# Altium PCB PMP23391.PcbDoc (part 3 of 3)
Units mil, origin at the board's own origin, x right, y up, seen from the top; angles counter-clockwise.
Board outline 5500 x 3250 mil, 2 copper layers (Top Layer, Bottom Layer), stack 62 mil thick; 163 components, 101 nets, 543 pads, 307 vias.
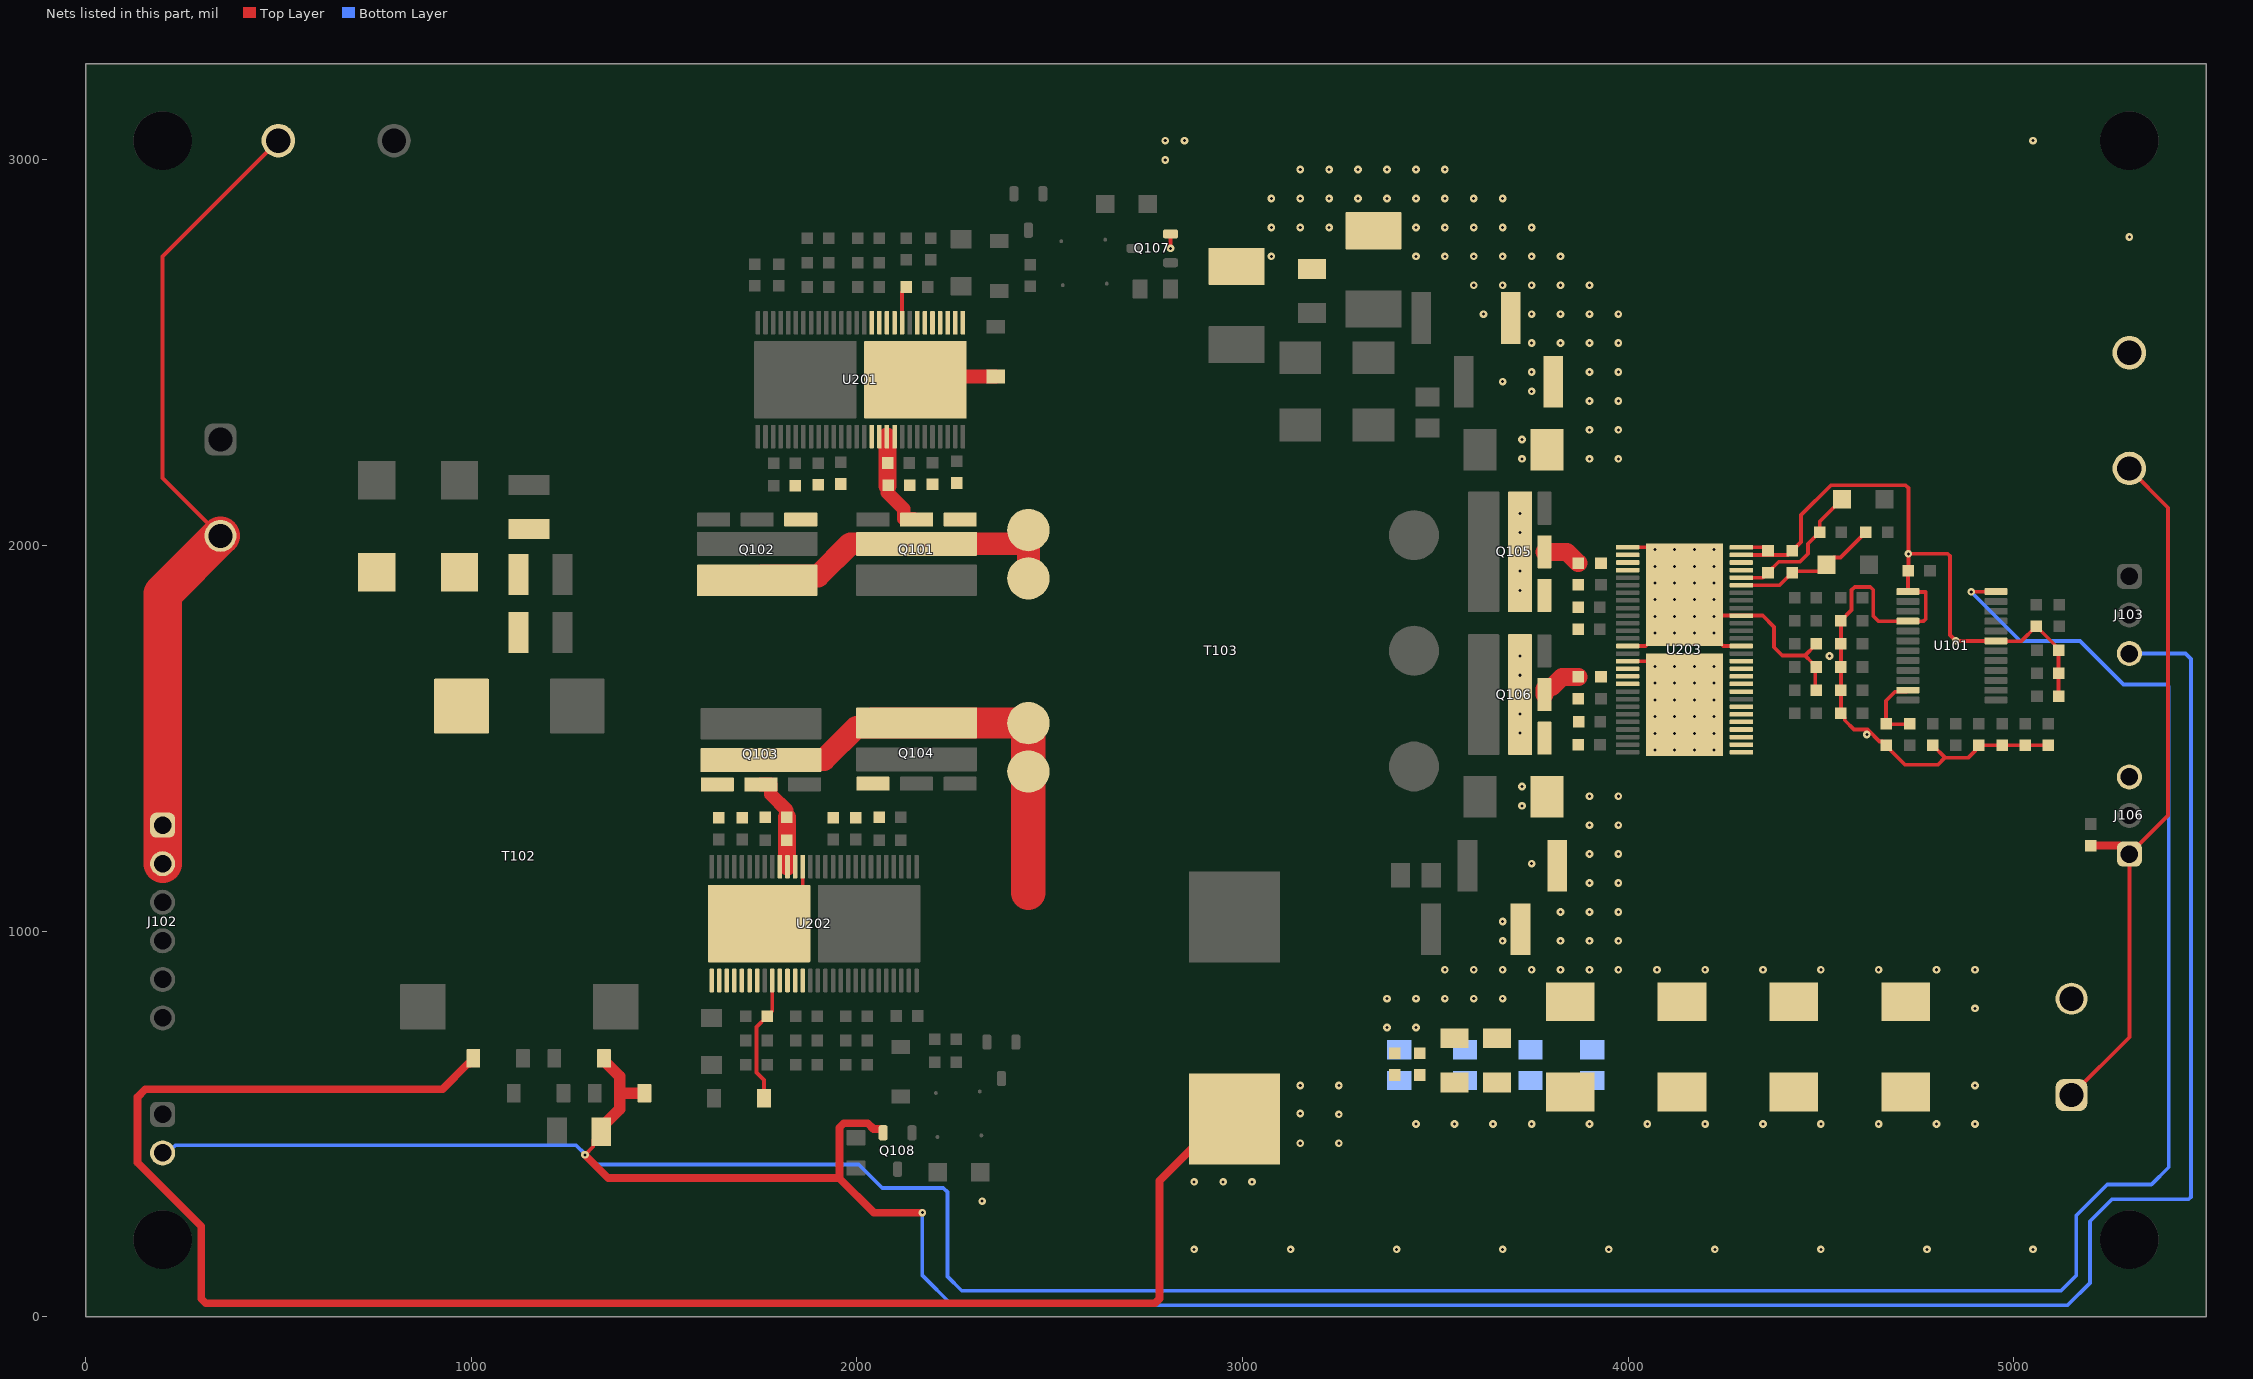
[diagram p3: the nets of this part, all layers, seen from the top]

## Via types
v1: diameter 20, hole 8, Top Layer to Bottom Layer, 211 vias
v2: diameter 19.68, hole 7.87, Top Layer to Bottom Layer, tented both sides, 96 vias

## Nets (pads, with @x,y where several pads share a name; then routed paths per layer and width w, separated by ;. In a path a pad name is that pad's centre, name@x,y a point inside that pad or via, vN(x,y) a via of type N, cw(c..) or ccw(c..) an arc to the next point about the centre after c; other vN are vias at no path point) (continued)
SGND: C101.2 C104.1 C105.1 C106.2 C109.1 C110.2 C111.2 C112.2 C113.1 C114.1 C115.2 C116.2 C119.2 C120.2 C121.2 C122.2 C123.2 C124.2 C125.2 C211.2 C212.1 C213.1 C214.1 C301.2 C302.2 C303.2 C304.2 D103.2 D104.2 D106.2 D107.2 J103.3 J104.2 J105.2 J106.3 Q105.4 Q105.5 Q106.4 Q106.5 Q107.2 Q108.2 R101.1 R102.1 R103.1 R104.2 R105.2 R106.1 R109.2 R110.2 R117.1 R118.1 R119.1 R120.1 R121.2 R126.1 R230.2 R235.2 R236.2 R301.2 TP104.1 U101.7 U101.12 U101.13 U101.16 U203.1 U203.2 U203.3 U203.4 U203.5 U203.6 U203.7 U203.9 U203.10 U203.11 U203.12 U203.13 U203.15 U203.19 U203.25 U203.26 U203.27 U203.28 U203.29 U203.30 U203.31 U203.32 U203.42 U203.44 U203.45 U203.46 U203.47 U203.57 U203.58 | length 18652.7
  Top Layer w9.84: v1(1295,420) 1316.42,441.42 1316.42,459.33 R103.1@1337.09,480 ; v1(2813.58,2770.82) Q107.2@2813.58,2808.22 ; v2(4223.15,1816.32) 4225.12,1818.29 U203.19@4294.02,1818.29 4349.13,1818.29 4378.66,1788.76 4378.66,1736.34 4400,1715 4458.89,1715 ; U203.27@4294.02,1975.77 4415.62,1975.77 C114.1@4425.91,1986.05 4448.85,2008.99 4448.85,2079.3 4525.96,2156.42 4719.94,2156.42 4727,2149.35 v1(4727,1978.61) C104.1@4727,1935 4725.83,1933.83 U101.13@4725.83,1880.75 ; U203.28@4294.02,1995.45 4353.51,1995.45 C113.1@4362.91,1986.05 ; C212.1@4485.4,1615.53 C211.2@4485.4,1678.52 ; R230.2@4485.4,1741.51 4458.89,1715 ; C211.2@4488,1685.89 4487.11,1685.89 4477.92,1695.08 4477.92,1695.97 4458.89,1715 ; R126.1@4668.74,1480.74 4718,1431.48 4803.48,1431.48 4822,1450 ; R126.1@4670,1482 4659.92,1492.08 4652.38,1492.08 4621.51,1522.94 4586.33,1522.94 4562.08,1547.2 4562.08,1554.92 C106.2@4552,1565 R110.2@4552,1625 R109.2@4552,1745 C110.2@4552,1805 4579.8,1832.8 4579.8,1884.89 4587.7,1892.8 4628.3,1892.8 4635.8,1885.3 4635.8,1817 4648.82,1803.98 U101.16@4725.83,1803.98 4766.38,1803.98 4772.14,1809.74 4772.14,1879.53 U101.13@4727.04,1879.53 ; C112.2@4790,1482 4822,1450 ; v1(4890,1880) 4890.37,1880.37 4953.8,1880.37 U101.12@4954.17,1880.75 ; R102.1@5090,1482 C111.2@4910,1482 4899.92,1471.92 4899.92,1467.28 4882.64,1450 4822,1450
  Top Layer w10: U203.44@3998.74,1700.18 U203.57@4050.98,1700.18 ; U203.42@3998.74,1739.55 4045.98,1739.55 4069.61,1763.17 v2(4069.61,1773.01) ; U203.29@3998.74,1995.45 U203.58@4063.7,1995.45 ; U203.58@4146.38,1872.42 4146.38,1839.94 4246.77,1739.55 U203.15@4294.02,1739.55 ; v1(4727,1978.61) 4829.14,1978.61 4835,1972.75 4835,1767.8 v1(4850,1752.8) U101.7@4954.17,1752.8 ; U101.7@4954.17,1751.68 5019.39,1751.68 C101.2@5058.6,1790.89 5106.6,1742.89 5106.6,1738.89 R106.1@5116.6,1728.89 R104.2@5116.6,1608.89
  Top Layer w20: v1(1295,420) 1355.31,359.69 1955.02,359.69 ; Q108.2@2068.39,477.24 2068.39,485.12 2066.57,486.93 2043.36,486.93 2028.36,501.93 1966.64,501.93 1955.02,490.31 1955.02,359.69 ; v1(2170,270) 2044.71,270 1955.02,359.69
  Top Layer w30: R103.1@1337.09,480 1337.09,490.83 1385,538.74 1385,581 ; D103.2@1344.37,670 1344.37,663.9 1385,623.27 1385,581 ; D104.2@1449.37,580 1386,580 1385,581
  Top Layer w47.24: Q106.5@3783.19,1613.64 3783.19,1627.38 3788.82,1633.01 3802.56,1633.01 3828.83,1659.28 R235.2@3870.79,1659.28 ; Q105.5@3783.19,1983.64 3841.7,1983.64 R236.2@3870.79,1954.55
  Bottom Layer w9.84: J104.2@200,425 213.32,425 233.32,445 1272.24,445 1295,422.24 v1(1295,420) 1320,395 2005.26,395 2065.93,334.33 2224.23,334.33 2235,323.57 2235,104.83 2272.04,67.8 5122.96,67.8 5157.8,102.63 5157.8,102.8 5162.2,107.2 5162.2,262.37 5242.63,342.8 5357.03,342.8 5402.2,387.97 5402.2,1634.23 5396.44,1640 5285,1640 5282.8,1642.2 5282.63,1642.2 5171.95,1752.89 5017.11,1752.89 v1(4890,1880) ; v1(2170,270) 2170,107.27 2247.35,29.92 5139.92,29.92 5197.8,87.8 5197.8,247.63 5255.17,305 5454.23,305 5460,310.77 5460,1705.49 5445.49,1720 J103.3@5300,1720
  other v1: 2325,300 3375,750 3450,750 4900,800 3375,825 3450,825 3525,825 3600,825 3675,825 3525,900 3600,900 3675,900 3750,900 3825,900 3900,900 3975,900 4075,900 4200,900 4350,900 4500,900 4650,900 4800,900 4900,900 3675,975 3825,975 3900,975 3975,975 3675,1025 3825,1050 3900,1050 3975,1050 3900,1125 3975,1125 3750,1175 3900,1200 3975,1200 3900,1275 3975,1275 3725,1325 3900,1350 3975,1350 3725,1375 4619.38,1510 3720.18,1513.64 3720.18,1563.64 3720.18,1613.64 3720.18,1663.64 3720.18,1713.64 4522.59,1713.64 3720.18,1883.64 3720.18,1933.64 3720.18,1983.64 3720.18,2033.64 3720.18,2083.64 3725,2225 3900,2225 3975,2225 3725,2275 3900,2300 3975,2300 3900,2375 3975,2375 3750,2400 3675,2425 3750,2450 3900,2450 3975,2450 3750,2525 3825,2525 3900,2525 3975,2525 3625,2600 3750,2600 3825,2600 3900,2600 3975,2600 3600,2675 3675,2675 3750,2675 3825,2675 3900,2675 3075,2750 3450,2750 3525,2750 3600,2750 3675,2750 3750,2750 3825,2750 5300,2800 3075,2825 3150,2825 3225,2825 3450,2825 3525,2825 3600,2825 3675,2825 3750,2825 3075,2900 3150,2900 3225,2900 3300,2900 3375,2900 3450,2900 3525,2900 3599.69,2900 3675,2900 3150,2975 3225,2975 3300,2975 3375,2975 3450,2975 3525,2975 2800,3000 2800,3050 2850,3050 5050,3050
  other v2: 4069.61,1469.86 4120.79,1469.86 4171.97,1469.86 4223.15,1469.86 4069.61,1513.17 4120.79,1513.17 4171.97,1513.17 4223.15,1513.17 4069.61,1556.47 4120.79,1556.47 4171.97,1556.47 4223.15,1556.47 4069.61,1599.78 4120.79,1599.78 4171.97,1599.78 4223.15,1599.78 4069.61,1643.09 4120.79,1643.09 4171.97,1643.09 4223.15,1643.09 4069.61,1686.4 4120.79,1686.4 4171.97,1686.4 4223.15,1686.4 4120.79,1773.01 4171.97,1773.01 4223.15,1773.01 4069.61,1816.32 4120.79,1816.32 4171.97,1816.32 4069.61,1859.62 4120.79,1859.62 4171.97,1859.62 4223.15,1859.62 4069.61,1902.93 4120.79,1902.93 4171.97,1902.93 4223.15,1902.93 4069.61,1946.24 4120.79,1946.24 4171.97,1946.24 4223.15,1946.24 4069.61,1989.55 4120.79,1989.55 4171.97,1989.55 4223.15,1989.55
SRA: C114.2 D108.1 R114.1 U203.23 | length 353.3
  Top Layer w9.84: U203.23@4294.02,1897.03 4392.88,1897.03 4429.36,1933.51 D108.1@4494.84,1933.51 ; D108.1@4514.88,1950 4533.58,1968.7 4550.7,1968.7 R114.1@4617,2035
SRB: C113.2 D105.1 R113.1 U203.24 | length 376.2
  Top Layer w9.84: U203.24@4294.02,1916.71 4349.57,1916.71 C113.2@4362.91,1930.05 4390.71,1957.84 4445.8,1957.84 4466.56,1978.61 4466.56,2004.56 R113.1@4497,2035 4497,2062.12 D105.1@4554.88,2120
SW_A: Q101.4 Q102.3 T103.1 T103.2 | length 821.7
  Top Layer w59.06: Q102.3@1743.58,1910 1754.55,1920.96 1899.36,1920.96 1983.38,2004.98 Q101.4@2145.65,2004.98 ; Q101.4@2155,2004.49 2444.49,2004.49 2445,2005 T103.2@2445,1914.92
SW_B: Q103.4 Q104.3 T103.5 T103.6 | length 1168.3
  Top Layer w59.06: Q103.4@1751.46,1443.54 1752.93,1445.02 1915.2,1445.02 1999.22,1529.04 Q104.3@2041.48,1529.04
  Top Layer w80: Q104.3@2040.98,1540.49 2041.48,1540 T103.5@2444.33,1540
  Top Layer w90: 2445,1100 T103.6@2445,1414.13 T103.5@2445,1539.33
VG_HOA: Q101.1 R208.1 R209.1 R212.1
VG_HOB: Q103.1 R221.1 R222.1 R225.1
VG_LOA: Q102.1 R210.1 R211.1 R213.1
VG_LOB: Q104.1 R223.1 R224.1 R226.1
VG_SRA: Q105.1 R233.1 R234.1 R236.1
VG_SRB: Q106.1 R231.1 R232.1 R235.1
VIN: C102.1 C103.1 C107.1 C108.1 J101.2 J102.1 J102.2 R108.1 T102.2 TP101.1 | length 2123.5
  Top Layer w10: J101.2@350,2025 200,2175 200,2750 TP101.1@500,3050
  Top Layer w100: J102.2@200,1175 J102.1@200,1275 200,1875 J101.2@350,2025
VOUT: C115.1 C116.1 C119.1 C120.1 C121.1 C123.1 C124.1 C125.1 C301.1 C302.1 C303.1 C304.1 D101.1 J105.1 J106.1 L101.2 R124.2 TP103.1 | length 6413.8
  Top Layer w10: J105.1@5150,575 5300,725 J106.1@5300,1200 5400,1300 5400,2098.14 5300,2198.14 TP103.1@5300,2200
  Top Layer w20: D101.1@1005.63,670 1005.63,663.9 997.72,655.98 991.61,655.98 925.63,590 155,590 135,570 135,400 300,235 300,46.72 311.72,35 2773.28,35 2785,46.72 2785,353.19 L101.2@2945,513.19 ; R124.2@5200,1222 5274.62,1222 5296.62,1200 J106.1@5300,1200
  other v1: 2875,175 3125,175 3400,175 3675,175 3950,175 4225,175 4500,175 4775,175 5050,175 2875,350 2950,350 3025,350 3150,450 3250,450 3450,500 3550,500 3650,500 3750,500 3900,500 4050,500 4200,500 4350,500 4500,500 4650,500 4800,500 4900,500 3250,525 3150,527.2 3150,600 3250,600 4900,600
VS_HOA: C203.2 C204.2 D202.2 Q101.5 R212.2 U201.1 U201.2 U201.3 U201.4 U201.5 U201.6 U201.7 U201.9 U201.10 U201.11 U201.12 U201.13 U201.44 U201.45 U201.46 U201.47 U201.57 | length 563.9
  Top Layer w9.84: U201.9@2117.6,2577.89 2117.6,2657.07 C203.2@2129.63,2669.1
  Top Layer w35.43: R212.2@2079.76,2154.67 2079.76,2136.84 2121.85,2094.74 2121.85,2069.74 2122.13,2069.47 Q101.5@2147.13,2069.47 ; U201.57@2152.05,2430.26 2160.33,2438.54 D202.2@2360,2438.54
  Top Layer w47.24: U201.46@2078.23,2282.62 2079.76,2281.09 R212.2@2079.76,2154.67
VS_HOB: C208.2 C209.2 D204.2 Q103.5 R225.2 U202.1 U202.2 U202.3 U202.4 U202.5 U202.6 U202.7 U202.9 U202.10 U202.11 U202.12 U202.13 U202.44 U202.45 U202.46 U202.47 U202.57 | length 791.1
  Top Layer w9.84: D204.2@1759.07,567.33 1759.07,614.09 1739.85,633.3 1739.85,751.79 C208.2@1767.65,779.59 1780.98,792.93 U202.9@1780.98,872.11
  Top Layer w10: U202.57@1746.54,1019.74 1764.33,1019.74 1859.72,1115.14 U202.44@1859.72,1167.38
  Top Layer w35.43: Q103.5@1751.46,1380.53 1776.46,1380.53 1776.73,1380.26 1776.73,1355.26 1818.83,1313.16 R225.2@1818.83,1295.33
  Top Layer w47.24: R225.2@1818.83,1295.33 C209.2@1818.83,1236.28 1818.83,1168.91 U202.46@1820.35,1167.38
VSENSE: R125.1 R126.2 U101.23 | length 189.1
  Top Layer w9.84: U101.23@4725.83,1624.84 4721.89,1620.91 4692.14,1620.91 4668.6,1597.36 4668.6,1536.89 R125.1@4728.6,1536.89
pads on no net: H201.0 H201.MH H202.0 H202.MH H203.0 H203.MH H204.0 H204.MH Q101.2 Q102.2 Q103.2 Q104.2 Q105.2 Q106.2 U201.14 U201.16 U201.43 U202.14 U202.16 U202.43 U203.14 U203.16 U203.43

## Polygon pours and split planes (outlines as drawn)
NetQ101_3 on Top Layer "TOP_LAYER_NETQ101_3_P025" (solid, remove dead copper, pour order 25): 825,900 650,725 270,725 270,1850 372.5,1952.5 475,1850 1900.36,1850 2000.36,1950 2329.71,1950 2329.71,1571.08 1990,1231.37 1990,900
SGND on Top Layer "TOP_LAYER_SGND_P035" (solid, remove dead copper, pour order 35): 2775,1275 3395,1895 3395,2665.22 2856.61,2665.22 2856.61,2873.39 2795,2935 2620,2935 2620,3250 5200,3250 5200,3000 5250,2950 5500,2950 5500,300 5250,300 5200,250 5200,0 300,0 300,250 250,300 0,300 0,470 1246.12,470 1341.12,375 2425,375 2775,725
PGND on Top Layer "TOP_LAYER_PGND_P034" (solid, remove dead copper, pour order 34): 2525,3250 2525,725 2350,550 2315.73,550 1885,980.73 1885,1849.55 250,1850 250,725 0,725 0,2950 250,2950 300,3000 300,3250
VOUT on Top Layer "TOP_LAYER_VOUT_P032" (solid, remove dead copper, pour order 32): 2820,645 2775,600 2775,0 5200,0 5200,250 5220,270 5220,645
NetC118_2 on Top Layer "TOP_LAYER_NETC118_2_P002" (solid, remove dead copper, pour order 2): 3629.45,1255 3629.45,1049.45 3515,935 3450,935 3450,1201.14 3508.03,1255
NetC118_1 on Top Layer "TOP_LAYER_NETC118_1_P031" (solid, remove dead copper, pour order 31): 3665,1765 3549.32,1765 3550.36,1635.36 3358.5,1443.5 3358.5,1110 3540,1110 3540,1255 3665,1255
NetC122_1 on Top Layer "TOP_LAYER_NETC122_1_P030" (solid, remove dead copper, pour order 30): 3430,2665 3430,2435 2905,2435 2905,2575 3055,2575 3145,2665
NetC117_2 on Top Layer "TOP_LAYER_NETC117_2_P029" (solid, remove dead copper, pour order 29): 3430,2335 3430,2665 3490,2665 3605,2550 3605,2335
VG_LOB on Top Layer "TOP_LAYER_VG_LOB_P003" (solid, remove dead copper, pour order 3): 1920,1280 2075,1280 2075,1398.54 2073.54,1400 2000,1400 2000,1390 1920,1310
VG_HOB on Top Layer "TOP_LAYER_VG_HOB_P004" (solid, remove dead copper, pour order 4): 1780,1278.03 1620,1278.03 1620,1398.03 1680.47,1398.03 1780,1298.5
VG_LOA on Top Layer "TOP_LAYER_VG_LOA_P009" (solid, remove dead copper, pour order 9): 1986.46,2168.03 1831.46,2168.03 1831.46,2049.5 1832.92,2048.03 1906.46,2048.03 1906.46,2058.03 1986.46,2138.03
VG_HOA on Top Layer "TOP_LAYER_VG_HOA_P011" (solid, remove dead copper, pour order 11): 2126.46,2170 2286.46,2170 2286.46,2050 2225.98,2050 2126.46,2149.53
VIN on Top Layer "TOP_LAYER_VIN_P014" (solid, remove dead copper, pour order 14): 285,2030 330,2075 1175,2075 1175,1505 810,1505
NetL101_1 on Top Layer "TOP_LAYER_NETL101_1_P015" (solid, remove dead copper, pour order 15): 3510,1760 3510,1655 3320,1465 3320,1115 3105.67,900.67 2824.33,900.67 2775,950 2775,1275 3294.64,1794.64 3475.36,1794.64
NetC117_1 on Top Layer "TOP_LAYER_NETC117_1_P016" (solid, remove dead copper, pour order 16): 3671.36,1805 3570,1805 3280,2095 3280,2335 3671.36,2335
VG_SRA on Top Layer "TOP_LAYER_VG_SRA_P026" (solid, remove dead copper, pour order 26): 3888.19,1758.64 3888.19,1913.64 3764.96,1913.64 3764.96,1836.87 3843.19,1758.64
VG_SRB on Top Layer "TOP_LAYER_VG_SRB_P028" (solid, remove dead copper, pour order 28): 3887.8,1622.15 3887.8,1462.15 3767.8,1462.15 3767.8,1522.62 3867.33,1622.15
NetQ101_3 on Bottom Layer "BOTTOM_LAYER_NETQ101_3_P021" (solid, remove dead copper, pour order 21): 1950,1850 2015,1785 2520,1785 2520,3225 2519.51,3224.51 2195,3224.51 2195,2815.34 2148.5,2768.84 2050,2768.84 2050,2195.96 2044.14,2190.1 1950,2190.1
VOUT on Bottom Layer "BOTTOM_LAYER_VOUT_P022" (solid, remove dead copper, pour order 22): 2820,645 2440,265 2310,265 2310,0 5200,0 5200,252.97 5350.35,403.32 5350.35,645
PGND on Bottom Layer "BOTTOM_LAYER_PGND_P027" (solid, remove dead copper, pour order 27): 2521.33,3249.46 2521.33,724.46 2346.33,549.46 1846.33,549.46 1746.33,649.46 1471.33,649.46 1396.33,724.46 -3.67,724.46 -3.67,2949.46 246.33,2949.46 296.33,2999.46 296.33,3249.46
SGND on Bottom Layer "BOTTOM_LAYER_SGND_P033" (solid, remove dead copper, pour order 33): 2775,1275 3395,1895 2620,2670 2620,3250 5200,3250 5200,3000 5250,2950 5500,2950 5500,300 5250,300 5200,250 5200,0 300,0 300,250 250,300 0,300 0,470 1246.12,470 1341.12,375 2425,375 2775,725

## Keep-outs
Keep-Out Layer:
  text ".Layer_Name" at 577,-858.49 h60

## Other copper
Top Layer:
  rectangle net SW_A: 2350,1860 2520,2095
  rectangle net NetC204_1: 2115,2200 2160,2310
  rectangle net NetR210_2: 1878.03,2200.8 1923.03,2310.8
  rectangle net NetC205_2: 1818.03,2200.8 1863.03,2310.8
  rectangle net PGND: 1735,2200 1805,2335
  rectangle net VS_HOA: 2152.05,2525 2280,2610
  rectangle net VS_HOA: 2035,2250 2100,2340
  rectangle net NetR211_2: 1938.03,2200.8 1983.03,2310.8
  rectangle net NetR208_2: 2175,2200 2220,2310
  rectangle net NetR209_2: 2235,2200 2280,2310
  region net NetR223_2: 2022.24,1248.41 1977.24,1248.41 1977.24,1138.41 2022.24,1138.41
  region net PGND: 2165.28,1249.2 2095.28,1249.2 2095.28,1114.2 2165.28,1114.2
  region net NetC210_2: 2076.26,1259.9 2037.24,1259.9 2037.24,1138.41 2076.26,1138.41
  region net NetR224_2: 1962.24,1248.41 1917.24,1248.41 1917.24,1138.41 1962.24,1138.41
  rectangle net VS_HOB: 1800,1115 1860,1200
  region net NetR221_2: 1725.28,1249.2 1680.28,1249.2 1680.28,1139.2 1725.28,1139.2
  region net NetR222_2: 1665.28,1249.2 1620.28,1249.2 1620.28,1139.2 1665.28,1139.2
  region net NetC209_1: 1785.28,1249.2 1740.28,1249.2 1740.28,1139.2 1785.28,1139.2
  rectangle net VS_HOA: 2035,2525 2120,2610
  rectangle net PGND: 1741.61,2525 1805,2610
  rectangle net SGND: 4238.19,1933.64 4323.19,2002.43
  rectangle net SGND: 4225.12,1617.04 4322.37,1703.64
  rectangle net SGND: 4230.16,1460.73 4323.19,1586.99
  region net SGND: 3858.79,2005.73 3858.79,1935.73 4051.92,1935.73 4051.92,2005.73
  rectangle net SGND: 3970.18,1663.21 4075.16,1703.64
  rectangle net VS_HOB: 1776.46,840 1865,940
  rectangle net VS_HOB: 1620,840 1745,940
  region net NetC214_2: 3917.71,1918.64 3917.71,1877.69 4027.71,1877.69 4027.71,1918.64
  region net NetR232_2: 3916.92,1505.73 3916.92,1460.73 4026.92,1460.73 4026.92,1505.73
  region net NetC213_2: 3916.92,1625.73 3916.92,1580.73 4026.92,1580.73 4026.92,1625.73
  region net NetR231_2: 3916.92,1565.73 3916.92,1520.73 4026.92,1520.73 4026.92,1565.73
  rectangle net SGND: 3873.19,1638.64 4028.19,1703.64
  region net NetR233_2: 3917.71,1862.7 3917.71,1817.7 4027.71,1817.7 4027.71,1862.7
  region net NetR234_2: 3917.71,1802.7 3917.71,1757.7 4027.71,1757.7 4027.71,1802.7
  rectangle net PGND: 2095,840 2157.41,935
  pour cut-out: 2580,1034.69 2445,1034.69 2445,1044.69 2580,1044.69
  pour cut-out: 4708.72,2165 4560,2165 4560,2160.05 3788.82,2160.05 3788.82,2140 4708.74,2140
  pour cut-out: 4027.3,1437.62 4590.62,1437.62 4603,1450 4600.86,1452.14 4026.92,1452.14
  pour cut-out: 2005,1480 2005,1410 1995,1410 1995,1480
  pour cut-out: 1902.11,1970 1885,1970 1885,2040 1902.11,2040
  pour cut-out: 3815,1750 3960,1750 3960,1669.77 3815.05,1669.77
  text ".Layer_Name" at 577,-858.49 h60
Bottom Layer:
  pour cut-out: 4756.05,1425 4482.47,1425 4515.3,1457.83 4753.46,1457.83 4753.62,1458
  text ".Layer_Name" at 577,-858.49 h60

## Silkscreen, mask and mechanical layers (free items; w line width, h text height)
Top Overlay:
  lines w5: 4380,2025 4461.23,2025 4461.23,1998.77 4468.5,1991.5 4477,1991.5 ; 5140.76,1728.89 5180.11,1728.89 5204,1705 5204,1656
  text "'.PRJ_Number'.PCB_Rev" at 950,3000 h120
  text ".Layer_Name" at 577,-858.49 h60
Bottom Overlay:
  text ".Layer_Name" at 577,-858.49 h60
Top Paste:
  text ".Layer_Name" at 577,-858.49 h60
Bottom Paste:
  text ".Layer_Name" at 577,-858.49 h60
Top Solder:
  text ".Layer_Name" at 577,-858.49 h60
  text ".Layer_Name" at 577,-858.49 h60
Bottom Solder:
  text ".Layer_Name" at 577,-858.49 h60
Drill Guide:
  text ".Layer_Name" at 577,-858.49 h60
M1 Board Outline:
  the board outline again, w10
  text ".Layer_Name" at 577,-858.49 h60
M2 Board Dimensions:
  rectangle: 0,-275 125,-150
  rectangle: 125,-400 500,-275
  lines w7: 0,-275 1000,-275 ; 125,-400 125,-150 ; 250,-400 250,-150 ; 500,-400 500,-150 ; 750,-400 750,-150 ; 0,-400 1000,-400 1000,-150 0,-150 0,-400
  text ".Layer_Name" at 577,-858.49 h60
M3 3D STEP Top:
  text ".Layer_Name" at 577,-858.49 h60
M4 3D STEP Bottom:
  text ".Layer_Name" at 577,-858.49 h60
M5 Assembly Top:
  lines w10: -292,-930.17 6308,-930.17 ; -292,-726.83 6310,-726.83 ; -292,-523.5 -292,-1133.5 3713,-1133.5 6310,-1133.5 6310,-523.5 -291.5,-523.5 -291.5,-1133.5 1284,-1133.5 ; 2173,-1133.5 2173,-523.5 ; 3440,-726.83 3440,-523.5 ; 4280,-726.83 4280,-523.5 ; 4902,-1140 4902,-937.17
  text "COMPONENTS MARKED 'DNP' SHOULD NOT BE POPULATED." at 1153.5,-318.5 h60
  text "ASSEMBLY VARIANT:" at 1153,-434 h60
  text ".VariantName" at 2189,-434 h60
  text "PCB VIEWED FROM TOP SIDE" at -228.5,-655.67 h60
  text "BOARD #:" at 2248,-655.67 h60
  text ".PRJ_Number" at 2793.5,-655.67 h60
  text "REV:" at 3638,-655.67 h60
  text ".PCB_Rev" at 3929.5,-655.67 h60
  text "SVN REV:" at 4476,-655.67 h60
  text ".VersionControl_RevNumber" at 4982,-655.67 h60
  text "TID #:" at 2248,-859 h60
  text ".TID" at 2793.5,-859 h60
  text "PLOT NAME =" at -228.5,-1064.34 h60
  text ".plot_File_Name" at 577,-1064.34 h60
  text "GENERATED    :" at 2250,-1064.34 h60
  text ".Print_Date" at 3119.5,-1064.34 h60
  text ".Print_Time" at 3848.5,-1064.34 h60
  text "TEXAS INSTRUMENTS" at 5113,-1064.34 h60
M6 Assembly Bottom:
  lines w10: -292.5,-727.33 6309.5,-727.33 ; -290.5,-930.67 6309.5,-930.67 ; 1115.5,-1140.5 1115.5,-937.67 ; 1737.5,-727.33 1737.5,-524 ; 2577.5,-727.33 2577.5,-524 ; 3844.5,-1134 3844.5,-524 ; 4733.5,-1134 6309,-1134 6309,-524 -292.5,-524 -292.5,-1134 2304.5,-1134 6309.5,-1134 6309.5,-524
  text "COMPONENTS MARKED 'DNP' SHOULD NOT BE POPULATED." at 6102,-318 h60
  text ".VariantName" at 5058,-434 h60
  text "ASSEMBLY VARIANT:" at 6097,-434 h60
  text ".VersionControl_RevNumber" at 1035.5,-656.17 h60
  text "SVN REV:" at 1541.5,-656.17 h60
  text ".PCB_Rev" at 2088,-656.17 h60
  text "REV:" at 2379.5,-656.17 h60
  text ".PRJ_Number" at 3224,-656.17 h60
  text "BOARD #:" at 3769.5,-656.17 h60
  text "PCB VIEWED FROM BOTTOM SIDE" at 6246,-656.17 h60
  text ".TID" at 3224,-859.5 h60
  text "TID #:" at 3769.5,-859.5 h60
  text "TEXAS INSTRUMENTS" at 904.5,-1064.84 h60
  text ".Print_Time" at 2169,-1064.84 h60
  text ".Print_Date" at 2898,-1064.84 h60
  text "GENERATED    :" at 3767.5,-1064.84 h60
  text ".plot_File_Name" at 5440.5,-1064.84 h60
  text "PLOT NAME =" at 6246,-1064.84 h60
M9 Title Sheet:
  drawing of 57 lines, arcs and shapes, not listed
  text "1" at 739.84,8036.5 h70
  text "2" at 3235.5,8036.5 h70
  text "3" at 5724.84,8036.5 h70
  text "4" at 8231.51,8036.5 h70
  text "5" at 10730.5,8036.5 h70
  text "6" at 13235.5,8036.5 h70
  text "A" at -416.5,6893.5 h70
  text "A" at 14383.5,6893.5 h70
  text "B" at -416.5,4513.5 h70
  text "B" at 14383.5,4513.5 h70
  text "C" at -416.5,2138.5 h70
  text "C" at 14383.5,2138.5 h70
  text "PROJECT TITLE:" at 11343.5,277.5 h45
  text ".PRJ_Title" at 11393.5,144.17 h70
  text "DESIGNED FOR:" at 11343.5,-23.5 h45
  text ".PRJ_Customer" at 11393.5,-163.5 h70
  text "D" at -416.5,-231.5 h70
  text "D" at 14383.5,-231.5 h70
  text "FILE NAME:" at 11343.5,-323.5 h45
  text ".PCB_File_Name_No_Path" at 11393.5,-443.5 h70
  text "Texas Instruments (TI) and/or its licensors do not warrant the accuracy or completeness of this specification" at 6374,-605.34 h45
  text "ENGINEER:" at 11343.5,-613.5 h45
  text "LAYOUT BY:" at 12848.5,-613.5 h45
  text "or any information contained therein. TI and/or its licensors do not warrant that this design will meet" at 6329.01,-718 h45
  text ".PRJ_Engineer" at 11393.5,-768.49 h70
  text ".PCB_Layout" at 12899,-768.49 h70
  text "the specifications, will be suitable for your application or fit for any particular purpose, or will operate in" at 6329.01,-830.67 h45
  text ".Layer_Name" at 577,-858.49 h60
  text "ALTIUM DESIGNER VERSION:" at 12848.5,-923.5 h45
  text "an implementation. TI and/or its licensors do not warrant that the design is production worthy. You should" at 6329.01,-943.33 h45
  text "completely validate and test your design implementation to confirm the system functionality for your application." at 6374,-1056 h45
  text ".print_Scale" at 11393.5,-1056.83 h70
  text ".Application_BuildNumber" at 12899,-1056.83 h70
  text "1" at 739.84,-1263.5 h70
  text "2" at 3235.5,-1263.5 h70
  text "3" at 5724.84,-1263.5 h70
  text "4" at 8231.51,-1263.5 h70
  text "5" at 10730.5,-1263.5 h70
  text "6" at 13235.5,-1263.5 h70
M10 Fab Notes:
  drawing of 189 lines, arcs and shapes, not listed
  text "DESIGN INFORMATION" at 12382.02,6356.17 h60
  text "MIN. TRACK WIDTH:" at 11737.46,6224.05 h60
  text "8" at 12833.7,6224.05 h60
  text "MIL" at 12988.46,6224.05 h60
  text "7.874" at 12667.32,6102.36 h60
  text "MIN. CLEARANCE:" at 11737.46,6099.92 h60
  text "MIL" at 12988.46,6099.92 h60
  text "MIN. VIA PAD SIZE:" at 11737.46,5975.8 h60
  text "24" at 12803.71,5975.8 h60
  text "MIL" at 12988.46,5975.8 h60
  text "0.05mm (2MIL)" at 12432.46,5845.9 h60
  text "MINIMUM ANNULAR RING" at 11408.23,5837.67 h60
  text "EXTERNAL" at 13140.46,5837.67 h60
  text "PER" at 11608.23,5727.55 h60
  text "IPC-D-275 CLASS 2 LEVEL C" at 11828.23,5727.54 h60
  text "MIL, HOLES" at 13316.46,5627.07 h60
  text "+/-" at 12924,5618.48 h60
  text "+/-" at 13778,5618.48 h60
  text "REGISTRATION TOLERANCES:" at 11408.23,5617.42 h60
  text "METAL" at 12608,5617.42 h60
  text "5" at 13184.2,5617.42 h60
  text "3" at 14017.2,5617.42 h60
  text "MIL" at 14133.46,5617.42 h60
  text "HOLE SIZE TOLERANCE (UNLESS OTHERWISE SPECIFIED):" at 11408.23,5519.1 h60
  text "+/-" at 13778,5516.23 h60
  text "3" at 14017.2,5515.17 h60
  text "MIL" at 14133.46,5515.17 h60
  text "MATERIAL:" at 11333.46,5377.52 h60
  text "FR-4 High Tg" at 12319.9,5249 h60
  text "X" at 12175.46,5241.01 h60
  text "FR-4" at 11754.46,5236.49 h60
  text "OTHER" at 13242.46,5236.49 h60
  text "62 MIL (1.6mm) +/-10%" at 12074.56,5093.46 h60
  text "X" at 11954.46,5091.01 h60
  text "THICKNESS:" at 11408.23,5085.24 h60
  text "OTHER" at 13359.46,5085.24 h60
  text "TOLERANCE:" at 11408.23,4946.92 h60
  text "X" at 12256.46,4946.92 h60
  text "ANSI IPC-6012 TYPE 3 CLASS 2" at 12434.48,4946.92 h60
  text "OTHER +/-" at 12434.46,4802.73 h60
  text "BOW & TWIST:" at 11408.23,4657.54 h60
  text "X" at 12256.46,4657.54 h60
  text "ANSI IPC-6012 TYPE 3 CLASS 2" at 12434.48,4657.54 h60
  text "OTHER +/-" at 12434.46,4510.85 h60
  text "DRILLING:" at 11333.46,4380.23 h60
  text "NC_DRILL FILES" at 13094.46,4275.04 h60
  text "REFERENCE:" at 11408.23,4271.1 h60
  text "X" at 12065.46,4271.01 h60
  text "AS SHOWN" at 12243.46,4271.1 h60
  text "X" at 12966.46,4271.1 h60
  text "OTHER" at 13392.46,4128.85 h60
  text "PTH COPPER THICKNESS:" at 11407.91,4125.32 h60
  text "X" at 12547.14,4125.32 h60
  text "20-30 um" at 12675.14,4125.32 h60
  text "BOARD FINISH:" at 11333.46,3977.73 h60
  text "SILKSCREEN:" at 11488.68,3867.6 h60
  text "X" at 12446.46,3867.6 h60
  text "TOP" at 12563.46,3867.6 h60
  text "X" at 12956.46,3867.6 h60
  text "BOTTOM" at 13074.46,3867.6 h60
  text "SILKSCREEN COLOR:" at 11488.68,3712.41 h60
  text "X" at 12445.46,3712.41 h60
  text "WHITE" at 12563.46,3712.41 h60
  text "OTHER" at 13074.46,3712.41 h60
  text "X" at 12576.46,3568.96 h60
  text "GREEN" at 12694.46,3568.96 h60
  text "OTHER" at 13312.46,3568.96 h60
  text "SOLDER RESIST COLOR:" at 11488.68,3562.1 h60
  text "X" at 12576.46,3414.71 h60
  text "MATTE" at 12694.46,3414.71 h60
  text "SEMI-GLOSS" at 13312,3414.07 h60
  text "IMMERSION GOLD (ENIG)" at 12394.46,3241.94 h60
  text "ENEPIG" at 13732,3234.72 h60
  text "SURFACE FINISH:" at 11333.46,3233.72 h60
  text "X" at 12216.46,3233.72 h60
  text "IMM. TIN/SILVER OR EQUIV" at 11663,3096.4 h60
  text "OTHER" at 13094.46,3092.47 h60
  text "ARRAY/PANEL:" at 11333.46,2937.09 h60
  text "CUT AND TRIM PER M1 BOARD OUTLINE" at 12394.46,2928.87 h60
  text "N.C. ROUTE" at 12394.46,2792.9 h60
  text "X" at 13082.46,2792.9 h60
  text "V. SCORE" at 13260.46,2792.9 h60
  text "CERTIFICATION:" at 11333.46,2663.77 h60
  text "MATERIALS AND WORKMANSHIP FOR ALL PCBS" at 12058.46,2663.77 h60
  text "TO MEET OR EXCEED THE REQUIREMENTS OF:" at 12058.46,2569.71 h60
  text "X" at 11695.97,2441.08 h60
  text "ANSI IPC-A-600F CLASS ->" at 11823.96,2441.08 h60
  text "X" at 13471.97,2441.08 h60
  text "2" at 13581.96,2441.08 h60
  text "1" at 13266.96,2439.58 h60
  text "3" at 13935.96,2439.58 h60
  text "X" at 12507.97,2293.39 h60
  text "RoHS" at 12635.96,2293.39 h60
  text "OTHER" at 13280.36,2293.39 h60
  text "PER ORDER" at 13677.42,2293.39 h60
  text "ALL BOARDS MUST MEET OR EXCEED UL94-V0 REQUIREMENTS." at 11361,2139.57 h60
  text "PCB MUST BEAR THE UL94V-0 UL REGISTERED MATERIAL ID NUMBER" at 11361,2023.5 h60
  text "ADDITIONAL REQUIREMENTS:" at 11333.46,1854.08 h60
  text "MICROSECTION:" at 11408.23,1746.95 h60
  text "YES" at 12313.96,1746.95 h60
  text "REQUIRED" at 13175.46,1602.62 h60
  text "BARE BOARD ELEC. TEST:" at 11408.23,1599.76 h60
  text "NONE" at 12713.96,1599.76 h60
  text "X" at 13057.46,1599.76 h60
  text "PER ORDER" at 13767.46,1599.76 h60
  text "XX MIL VIAS REQUIRE NON-CONDUCTIVE FILL AND PLANARIZE" at 11576.38,1394.82 h59
  text "XX MIL VIAS REQUIRE CONDUCTIVE FILL AND PLANARIZE" at 11584.38,1290.84 h60
  text "OUTER XX MIL TRACES REQUIRE 50 OHM SINGLE-ENDED IMPEDANCE" at 11583.39,1127.46 h58
  text "LAYER 2 & 3 (INNER LAYERS) XX MIL WIDE, XX MIL SPACE / TRACES REQUIRE 100 OHM DIFFERENTIAL IMPEDANCE" at 11575.39,891.74 h60
  text ".Layer_Name" at 577,-858.49 h60
M11 Gerber Information:
  lines w10: -292,-930.17 6308,-930.17 ; -292,-726.83 6310,-726.83 ; -292,-523.5 -292,-1133.5 3713,-1133.5 6310,-1133.5 6310,-523.5 -291.5,-523.5 -291.5,-1133.5 1284,-1133.5 ; 2173,-1133.5 2173,-523.5 ; 3440,-726.83 3440,-523.5 ; 4280,-726.83 4280,-523.5 ; 4902,-1140 4902,-937.17
  text "ALL ARTWORK VIEWED FROM TOP SIDE" at -228.5,-655.67 h60
  text "BOARD #:" at 2248,-655.67 h60
  text ".PRJ_Number" at 2793.5,-655.67 h60
  text "REV:" at 3638,-655.67 h60
  text ".PCB_Rev" at 3929.5,-655.67 h60
  text "SVN REV:" at 4476,-655.67 h60
  text ".VersionControl_RevNumber" at 4982,-655.67 h60
  text "LAYER NAME =" at -228.5,-858.49 h60
  text "TID #:" at 2248,-859 h60
  text ".TID" at 2793.5,-859 h60
  text "PLOT NAME =" at -228.5,-1064.34 h60
  text ".plot_File_Name" at 577,-1064.34 h60
  text "GENERATED    :" at 2250,-1064.34 h60
  text ".Print_Date" at 3119.5,-1064.34 h60
  text ".Print_Time" at 3848.5,-1064.34 h60
  text "TEXAS INSTRUMENTS" at 5113,-1064.34 h60
M12 Stackup:
  drawing of 191 lines, arcs and shapes, not listed
  text "Layer" at 9821.59,7874.94 h60
  text "Name" at 10231.51,7874.94 h60
  text "Material" at 11161.25,7874.94 h60
  text "Thickness" at 12021.02,7874.94 h60
  text "Constant" at 12670.85,7874.94 h60
  text "Board Layer Stack" at 13240.71,7874.94 h60
  text "Top Overlay" at 10231.51,7754.94 h60
  text "Top Solder" at 10231.51,7634.94 h60
  text "Solder Resist" at 11161.25,7634.94 h60
  text "0.40mil" at 12021.02,7634.94 h60
  text "3.5" at 12670.85,7634.94 h60
  text "1" at 9821.59,7514.94 h60
  text "Top Layer" at 10231.51,7514.94 h60
  text "1.40mil" at 12021.02,7514.94 h60
  text "Dielectric1" at 10231.51,7394.94 h60
  text "FR-4 High Tg" at 11161.25,7394.94 h60
  text "59.20mil" at 12021.02,7394.94 h60
  text "4.8" at 12670.85,7394.94 h60
  text "2" at 9821.59,7274.94 h60
  text "Bottom Layer" at 10231.51,7274.94 h60
  text "1.40mil" at 12021.02,7274.94 h60
  text "Bottom Solder" at 10231.51,7154.94 h60
  text "Solder Resist" at 11161.25,7154.94 h60
  text "0.40mil" at 12021.02,7154.94 h60
  text "3.5" at 12670.85,7154.94 h60
  text "Bottom Overlay" at 10231.51,7034.94 h60
  text ".Layer_Name" at 577,-858.49 h60
M13 Component Bodies Top:
  text ".Layer_Name" at 577,-858.49 h60
M14 Component Bodies Bottom:
  text ".Layer_Name" at 577,-858.49 h60
M15 Courtyards Top:
  text ".Layer_Name" at 577,-858.49 h60
M16 Courtyards Bottom:
  text ".Layer_Name" at 577,-858.49 h60
Drill Drawing:
  circle w10: c7386.22,6243.07 r27.63
  lines w10: 7358.59,5897.74 7413.85,5897.74 7386.22,5842.48 7358.59,5897.74 ; 7358.59,5966.81 7413.85,5966.81 7413.85,6022.06 7358.59,6022.06 7358.59,5966.81 ; 7358.59,6104.94 7372.41,6104.94 7386.22,6091.12 7400.03,6104.94 7413.85,6104.94 7400.03,6118.75 7413.85,6132.56 7400.03,6132.56 7386.22,6146.38 7372.41,6132.56 7358.59,6132.56 7372.41,6118.75 7358.59,6104.94 ; 7358.59,6353.58 7372.41,6353.58 7372.41,6339.77 7400.03,6339.77 7400.03,6353.58 7413.85,6353.58 7413.85,6381.2 7400.03,6381.2 7400.03,6395.02 7372.41,6395.02 7372.41,6381.2 7358.59,6381.2 7358.59,6353.58 ; 7358.59,6464.09 7386.22,6477.9 7413.85,6464.09 7400.03,6491.71 7413.85,6519.34 7386.22,6505.52 7358.59,6519.34 7372.41,6491.71 7358.59,6464.09
  lines w12: 7308.5,5805.19 10539.99,5805.19 ; 7308.5,6551.11 10539.99,6551.11 ; 7646.36,5680.87 7646.36,6675.43 ; 7978.37,5680.87 7978.37,6675.43 ; 8614.93,5680.87 8614.93,6675.43 ; 8874.07,5680.87 8874.07,6675.43 ; 9249.23,5680.87 9249.23,6675.43 ; 9973.56,5680.87 9973.56,6675.43 ; 7308.5,5680.87 10539.99,5680.87 10539.99,6675.43 7308.5,6675.43 7308.5,5680.87
  text "Symbol" at 7383.09,6588.4 h72
  text "Quantity" at 7683.66,6588.4 h72
  text "Finished Hole Size" at 8015.66,6588.4 h72
  text "Plated" at 8652.22,6588.4 h72
  text "Hole Type" at 8911.36,6588.4 h72
  text "Drill Layer Pair" at 9286.52,6588.4 h72
  text "Hole Tolerance" at 10010.85,6588.4 h72
  text "4" at 7683.66,6464.09 h60
  text "152.00mil (3.861mm)" at 8015.66,6464.09 h60
  text "NPTH" at 8652.22,6464.09 h60
  text "Round" at 8911.36,6464.09 h60
  text "Top Layer - Bottom Layer" at 9286.52,6464.09 h60
  text "96" at 7683.66,6339.77 h60
  text "7.87mil (0.200mm)" at 8015.66,6339.77 h60
  text "PTH" at 8652.22,6339.77 h60
  text "Round" at 8911.36,6339.77 h60
  text "Top Layer - Bottom Layer" at 9286.52,6339.77 h60
  text "211" at 7683.66,6215.44 h60
  text "8.00mil (0.203mm)" at 8015.66,6215.44 h60
  text "PTH" at 8652.22,6215.44 h60
  text "Round" at 8911.36,6215.44 h60
  text "Top Layer - Bottom Layer" at 9286.52,6215.44 h60
  text "14" at 7683.66,6091.12 h60
  text "45.28mil (1.150mm)" at 8015.66,6091.12 h60
  text "PTH" at 8652.22,6091.12 h60
  text "Round" at 8911.36,6091.12 h60
  text "Top Layer - Bottom Layer" at 9286.52,6091.12 h60
  text "4" at 7683.66,5966.81 h60
  text "62.99mil (1.600mm)" at 8015.66,5966.81 h60
  text "PTH" at 8652.22,5966.81 h60
  text "Round" at 8911.36,5966.81 h60
  text "Top Layer - Bottom Layer" at 9286.52,5966.81 h60
  text "4" at 7683.66,5842.48 h60
  text "63.00mil (1.600mm)" at 8015.66,5842.48 h60
  text "PTH" at 8652.22,5842.48 h60
  text "Round" at 8911.36,5842.48 h60
  text "Top Layer - Bottom Layer" at 9286.52,5842.48 h60
  text "333 Total" at 7683.66,5718.16 h60
  text ".Layer_Name" at 577,-858.49 h60
M17 Embedded Cavity:
  text ".Layer_Name" at 577,-858.49 h60
M18 Embedded Assembly:
  text ".Layer_Name" at 577,-858.49 h60
M19 Embedded Keepout:
  text ".Layer_Name" at 577,-858.49 h60

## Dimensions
0,-400 to 1000,-400 on M2 Board Dimensions
0,3250 to 5500,0 on M2 Board Dimensions
5500,0 to 0,3250 on M2 Board Dimensions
